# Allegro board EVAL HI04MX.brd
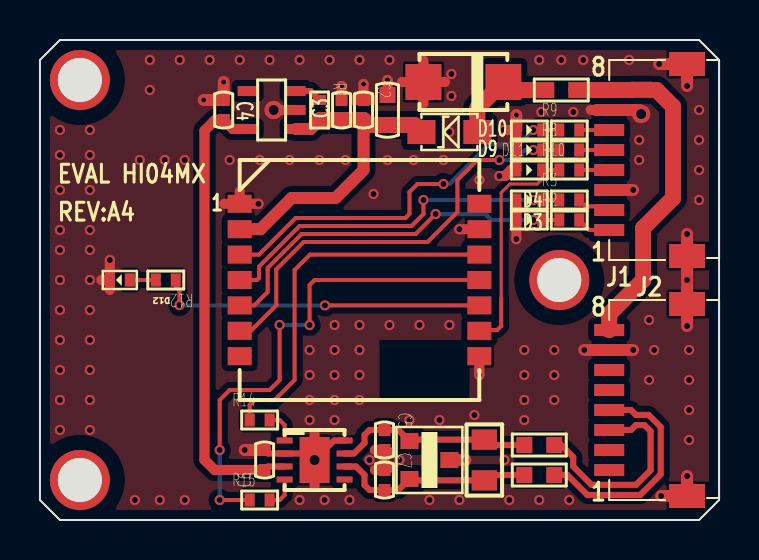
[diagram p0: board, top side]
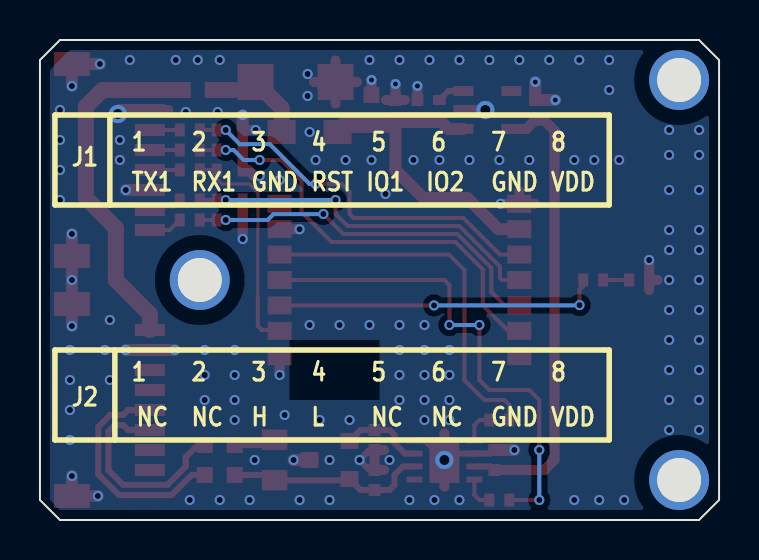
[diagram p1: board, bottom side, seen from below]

Outline 34 x 24 mm; copper layers: TOP, BOTTOM. Coordinates in mm from the lower left corner of the outline.
Outline path: 0,23 0,1 1,0 33,0 34,1 34,23 33,24 1,24 0,23

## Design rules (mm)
constraint set DEFAULT: min track width 0.152
net group CAN2: nets H L

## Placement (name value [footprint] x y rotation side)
C1  10uF  [C0603]  17.4 20.5 270 top
C2  0.1uF  [C0402]  16.2 20.5 270 top
C3  1uF  [C0402]  15.1 20.5 90 top
C4  1uF  [C0402]  9.2 20.5 270 top
C5  100pF  [C0402]  17.25 4 270 top
C6  0.1uF  [C0402]  11.25 3 90 top
C7  100pF  [C0402]  17.25 2 270 top
D1  RB160MM-60TR  [SOD123FL]  20.5 19.4 0 top
D2  SDD32A05L01  [DO-214AC]  21.2 21.9 180 top
D3  SBD52C05L01  [SOD-523]  24.5 15 0 top
D4  SBD52C05L01  [SOD-523]  24.5 16 0 top
D9  SBD52C05L01  [SOD-523]  24.5 18.5 0 top
D10  SBD52C05L01  [SOD-523]  24.5 19.5 0 top
D11  SBD52C05L01  [SOD-523]  24.5 17.5 0 top
D12  GREEN  [LED0402]  4 12 180 top
D13  SM24CANB-02HTG  [SOT23-3-0_95]  19.5 3 270 top
F1  100mA  [F0603]  25 3.75 180 top
F2  100mA  [F0603]  25 2.25 180 top
F3  300mA  [F0603]  26.1 21.5 180 top
H1  HOLE  [HOLE-2-MM]  2 22 0 top
H2  HOLE  [HOLE-2-MM]  2 2 0 top
H3  HOLE  [HOLE-2-MM]  26 12 0 top
J1  CON10  [5015680807_1]  28.5 18 270 top
J2  CON10  [5015680807_1]  28.5 6 270 top
R1  1K  [R0402]  14 20.5 270 top
R2  33R  [R0402]  26.5 15 0 top
R3  33R  [R0402]  26.5 16 0 top
R8  33R  [R0402]  26.5 18.5 0 top
R9  33R  [R0402]  26.5 19.5 0 top
R10  33R  [R0402]  26.5 17.5 0 top
R12  1K  [R0402]  6.3 12 180 top
R13  120R/DNP  [R0805]  22.25 3 90 top
R14  1K  [R0402]  11 5 0 top
R15  1K  [R0402]  11 1 0 top
U1  SPX3819M5-L-3-3/TR  [SOT23-5-0_95]  11.6 20.5 90 top
U2  HI04MX  [HI03_HI04MX]  16 12 0 top
U3  SIT3051TK  [HVSON8]  13.75 3 0 top

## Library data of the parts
C1-C7 = Capacity_Nonpolarity
D1 = diode
D2-D4 D9-D11 = DIODE BI-DIR TRIG
D12 = LED
D13 = BAT54A/SOT
F1-F3 = Fuse
H1-H3 = HOLE
J1 J2 = CON10
R1-R3 R8-R10 R12-R15 = Res
U1 = XC6210
U2 = HI04MX
U3 = SIT3051TK

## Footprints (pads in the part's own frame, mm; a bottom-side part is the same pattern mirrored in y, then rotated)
5015680807_1
  rect 0.6x1.5 smd: 1(3.5,0) 2(2.5,0) 3(1.5,0) 4(0.5,0) 5(-0.5,0) 6(-1.5,0) 7(-2.5,0) 8(-3.5,0)
  rect 1.2x1.8 smd: 9(4.8,3.9) 10(-4.8,3.9)
C0402
  rect 0.6x0.6 smd: 1(-0.5,0) 2(0.5,0)
C0603
  rect 0.8x0.8 smd: 1(-0.75,0) 2(0.75,0)
DO-214AC
  rect 1.8x1.8 smd: 1(2,0) 2(-2,0)
F0603
  rect 0.8x0.8 smd: 1(-0.75,0) 2(0.75,0)
HI03_HI04MX
  rect 1.2x0.9 smd: 1(-6,3.81) 2(-6,2.54) 3(-6,1.27) 4(-6,0) 5(-6,-1.27) 6(-6,-2.54) 7(-6,-3.81) 8(6,-3.81) 9(6,-2.54) 10(6,-1.27) 11(6,0) 12(6,1.27) 13(6,2.54) 14(6,3.81)
HOLE-2-MM
  round 3 hole 2.2: 1(0,0)
HVSON8
  rect 0.8x0.3 smd: 1(-1.5,0.975) 2(-1.5,0.325) 3(-1.5,-0.325) 4(-1.5,-0.975) 5(1.5,-0.975) 6(1.5,-0.325) 7(1.5,0.325) 8(1.5,0.975)
  rect 1.5x2.3 smd: 9(0,0)
LED0402
  rect 0.5x0.65 smd: 1(-0.5,0) 2(0.5,0)
R0402
  rect 0.5x0.65 smd: 1(-0.5,0) 2(0.5,0)
R0805
  rect 1.016x1.27 smd: 1(-1.016,0) 2(1.016,0)
SOD123FL
  rect 1.4x1.2 smd: 1(1.4,0) 2(-1.4,0)
SOD-523
  rect 0.5x0.65 smd: 1(-0.65,0) 2(0.65,0)
SOT23-3-0_95
  rect 0.8x0.9 smd: 1(-0.95,-1) 2(0.95,-1) 3(0,1)
SOT23-5-0_95
  rect 0.5x1 smd: 1(-0.95,-1.2) 2(0,-1.2) 3(0.95,-1.2) 4(0.95,1.2) 5(-0.95,1.2)

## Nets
GND: C1.1 C2.1 C3.2 C4.1 C5.2 C6.2 C7.1 D2.1 D3.1 D4.1 D9.1 D10.1 D11.1 D12.2(-) D13.3 J1.3 J1.7 J1.9 J1.10 J2.7 J2.9 J2.10 U1.2(VSS) U2.1 U2.8 U2.13 U3.2 U3.8 U3.9
VCC: F3.1 J1.8 J2.8
VDD: C1.2 C2.2 C3.1 D1.2 R1.2 U1.1 U2.2(VDD)
CAN_RX: R15.1 U2.11
CAN_TX: R14.1 U2.12
DP3V3: C4.2 C6.1 U1.5 U3.3(VCC)
H: F1.1 J2.3
IO1: D9.2 R8.1 U2.6
IO2: D10.2 R9.1 U2.3
IO5: R12.1 U2.10
IO_1: J1.5 R8.2
IO_2: J1.6 R9.2
L: F2.1 J2.4
NRST: J1.4 R10.2
RST: D11.2 R10.1 U2.9
RXD1: D4.2 R3.1 U2.4
TXD1: D3.2 R2.1 U2.5
USART1_RX: J1.2 R3.2
USART1_TX: J1.1 R2.2
N2198535: D12.1 R12.2
N2224750: R1.1 U1.3
N2242059: C5.1 D13.1 F1.2 R13.2 U3.7
N2242241: R14.2 U3.1
N2242331: C7.2 D13.2 F2.2 R13.1 U3.6
N2242381: R15.2 U3.4
N2269430: D1.1(P) D2.2 F3.2

Pads without a net: H1 1; H2 1; H3 1; J2 1 2 5 6; U1 4; U2 7 14; U3 5

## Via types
v1: diameter 0.508, hole 0.305, TOP to BOTTOM, 141 vias
v2: diameter 0.914, hole 0.508, TOP to BOTTOM, 3 vias
v3: diameter 0.508, hole 0.254, TOP to BOTTOM, 6 vias

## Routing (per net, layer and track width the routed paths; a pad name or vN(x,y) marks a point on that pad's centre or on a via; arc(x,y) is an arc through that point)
GND: length 52.6
  TOP w0.305: 12.25,3.33 U3.2 12.25,3.33 ; 12.25,3.33 13.42,3.33 v2(13.75,3) 14.72,3.97 U3.8 ; 12.25,3.33 11.42,3.33 C6.2 ; C7.1 17.5,2.5 v1(18,3) 17.5,3.5 C5.2
  TOP w0.5: 16.77,3.5 C5.2 17.25,3.02 ; 19.2,20.82 D2.1 ; D2.1 18.12,21.9 ; D2.1 19.2,22.98 ; D2.1 20.28,21.9 ; 10,16.44 U2.1 9.22,15.81 ; 29.43,20.5 J1.7 27.57,20.5 ; 3.5,11.5 D12.2 3.07,12 ; 13.75,4.33 v2(13.75,3) 13.75,1.67 ; 15.72,21 C2.1 16.68,21 ; 17.25,2.98 C7.1 16.77,2.5
  TOP w0.508: D12.2 v1(3.5,13) ; v1(23.85,14.05) D3.1 D4.1 ; U2.13 v1(21,14.54) ; U1.2 v2(11.7,20.5) ; C1.1 v3(17.4,22) ; U2.1 v1(10.94,15.81) ; C2.1 v3(16.2,21.8) ; C3.2 v3(15.1,21.7) ; v1(23.2,19.5) D10.1 D9.1 D11.1 23.58,17.5 23.28,17.2 v1(23,17.2) ; U2.8 v1(22,7.25)
  TOP w0.6: v1(31,22.8) J1.10 v1(32.4,21.7) ; v2(30.1,20.3) 30.1,20.4 30,20.5 J1.7 ; v3(9.2,21.9) C4.1 v3(8.2,21) ; v1(27.25,8.5) J2.7 v1(29.7,8.5) ; v1(32.4,2.2) J2.9 v1(31.1,1.2) ; J1.3 v1(29.7,16.5) ; D13.3 v1(21.3,3) ; C6.2 v1(10.25,3.5) ; D10.1 v3(23.85,20.25) ; v1(32.4,14.3) J1.9 v1(32.4,12) J2.10 v1(32.4,9.7)
  vias: v1(1,19.5) v1(1,18.25) v1(1,16.5) v1(1,14.5) v1(1,13.5) v1(1,12) v1(1,10.5) v1(1,9) v1(1,7.5) v1(1,6) v1(1,4.5) v1(2.5,19.5) v1(2.5,18.25) v1(2.5,16.5) v1(2.5,14.5) v1(2.5,13.5) v1(2.5,12) v1(2.5,10.5) v1(2.5,9) v1(2.5,7.5) v1(2.5,6) v1(2.5,4.5) v1(4.75,1) v1(5,18) v1(5.5,23) v1(5.5,21.5) v1(6,1) v1(6.25,18) v1(7,23) v1(7.25,18) v1(7.25,1) v1(8.5,23) v1(9.5,18) v1(10,23) v1(11,18) v1(11.5,23) v1(12.5,18) v1(13,23) v1(13,1) v1(13.5,8.5) v1(13.5,7.25) v1(13.5,6) v1(13.5,5) v1(14,18) v1(14.25,1) v1(14.5,23) v1(14.75,9.75) v1(14.75,8.5) v1(14.75,7.25) v1(14.75,6) v1(14.75,5) v1(15.3,18) v1(15.5,1) v1(16,23) v1(16,9.75) v1(16,8.5) v1(16,7.25) v1(16,6) v1(16.5,3) v1(16.7,16.3) v1(17.4,18) v1(17.5,23) v1(17.5,9.75) v1(18.5,5) v1(18.7,18) v1(19,9.75) v1(19.5,3) v1(19.5,1) v1(20,5) v1(20.2,18) v1(20.5,19.4) v1(20.5,9.75) v1(20.6,22.3) v1(20.6,21.2) v1(21,1) v1(21.75,5.25) v1(22,17) v1(23.25,3) v1(23.5,1) v1(24.25,8.5) v1(24.25,7.25) v1(24.25,6) v1(24.25,5) v1(25,23) v1(25,1) v1(25.1,20.4) v1(25.75,8.5) v1(25.75,7.25) v1(25.75,6) v1(26.1,23) v1(26.5,1) v1(26.7,20.4) v1(27.2,23) v1(29.5,23) v1(30,19) v1(30,18) v1(30.5,10) v1(30.5,7) v1(30.75,8.5) v1(32.5,8.5) v1(32.5,7) v1(32.5,5.5) v1(32.5,4) v1(33,20.5) v1(33,19) v1(33,17.5) v1(33,16)
VCC: length 17.7
  TOP w0.8: J2.8 28.5,10.3 30.2,12 30.2,14.6 31.7,16.1 31.7,20.67 30.87,21.5 30.57,21.5 30.56,21.51 29.64,21.51 29.63,21.5 J1.8 F3.1
VDD: length 16.7
  TOP w0.6: U1.1 13.55,19.55 R1.2 ; C2.2 16.2,17.5 14.8,16.1 12.6,16.1 11.04,14.54 U2.2
  TOP w0.8: D1.2 18.75,19.75 C1.2 16.45,19.75 C2.2 C3.1 R1.2
CAN_RX: length 24.8
  TOP w0.203: v1(9,3.5) 9,6 9.5,6.5 11.5,6.5 12,7 v1(12,9.75) ; v1(13.5,9.75) 13.5,11.75 13.75,12 U2.11 ; v1(9,1) R15.1
  BOTTOM w0.203: v1(9,3.5) v1(9,1) ; v1(13.5,9.75) v1(12,9.75)
CAN_TX: length 18.6
  TOP w0.203: U2.12 13.52,13.27 12.75,12.5 12.75,7 11.75,6 10.75,6 10.5,5.75 R14.1
DP3V3: length 23.3
  TOP w0.305: C6.1 11.42,2.68 U3.3
  TOP w0.508: C6.1 8.75,2.5 8.24,3.01 8.24,19.47 8.77,20 C4.2 9.65,19.55 U1.5
H: length 10.5
  TOP w0.305: F1.1 26.1,3.75 26.7,3.15 26.7,2.68 27.62,1.76 29.84,1.76 30.57,2.49 30.57,4.44 30.27,4.75 29.83,4.75 29.59,4.5 J2.3
IO1: length 21.7
  TOP w0.203: U2.6 10.56,9.46 11.83,10.73 11.83,12.53 13.2,13.9 19.4,13.9 20.9,15.4 20.9,17 21.9,18 v1(23,18) ; R8.1 D9.2 v1(24.7,18.5)
  BOTTOM w0.203: v1(24.7,18.5) 24.3,18.5 23.8,18 v1(23,18)
IO2: length 19.2
  TOP w0.203: U2.3 10.97,13.27 12.8,15.1 18.3,15.1 18.5,15.3 18.5,16.4 18.9,16.8 v1(20.2,16.8) ; v1(24.7,19.5) D10.2 R9.1
  BOTTOM w0.203: v1(20.2,16.8) 20.5,16.8 22.49,18.79 23.99,18.79 v1(24.7,19.5)
IO5: length 16.4
  TOP w0.203: v1(6.99,10.75) 6.99,11.51 6.8,11.7 R12.1 ; U2.10 v1(14.27,10.73)
  BOTTOM w0.203: v1(6.99,10.75) 7,10.73 v1(14.27,10.73)
IO_1: length 1.5
  TOP w0.203: J1.5 R8.2
IO_2: length 1.5
  TOP w0.203: J1.6 R9.2
L: length 11.5
  TOP w0.305: F2.1 26.41,2.25 27.41,1.25 30.05,1.25 31.08,2.28 31.08,4.65 30.48,5.25 29.83,5.25 29.59,5.5 J2.4
NRST: length 1.5
  TOP w0.203: R10.2 J1.4
RST: length 11.5
  TOP w0.152: 23.09,11.1 23.09,16.37 23.52,16.8 24.9,16.8 25.15,17.05 D11.2
  TOP w0.203: D11.2 R10.1 ; U2.9 22.04,9.5 22.89,9.5 23.09,9.7 23.09,11.1
RXD1: length 18.4
  TOP w0.203: v1(24.7,16) D4.2 R3.1 ; U2.4 10.87,12 10.97,12.1 10.97,12.67 13,14.7 18.6,14.7 19.2,15.3 v1(19.2,16)
  BOTTOM w0.203: v1(24.7,16) v1(19.2,16)
TXD1: length 18.7
  TOP w0.203: U2.5 10.73,10.73 11.4,11.4 11.4,12.6 13.1,14.3 18.81,14.3 v1(19.81,15.3) ; R2.1 D3.2 v1(24.7,15)
  BOTTOM w0.203: v1(19.81,15.3) 19.82,15.29 22.31,15.29 22.6,15 v1(24.7,15)
USART1_RX: length 1.7
  TOP w0.203: R3.2 27.32,15.68 28.32,15.68 J1.2
USART1_TX: length 1.7
  TOP w0.203: J1.1 27.5,14.5 R2.2
N2198535: length 1.3
  TOP w0.203: D12.1 R12.2
N2224750: length 1.4
  TOP w0.3: R1.1 13.55,21.45 U1.3
N2242059: length 10.1
  TOP w0.305: U3.7 15.25,3.33 15.72,3.33 16.25,3.85 16.25,4.25 16.5,4.5 C5.1 17.95,4.5 D13.1 18.57,4.02 R13.2 22.52,3.75 F1.2
N2242241: length 1.6
  TOP w0.203: R14.2 12,5 12.25,4.75 U3.1
N2242331: length 10.1
  TOP w0.305: F2.2 22.52,2.25 R13.1 18.57,1.98 D13.2 17.95,1.5 C7.2 16.5,1.5 16.25,1.75 16.25,2.25 15.82,2.68 U3.6
N2242381: length 1.6
  TOP w0.203: U3.4 12.25,1.25 12,1 R15.2
N2269430: length 5.4
  TOP w0.8: F3.2 23.6,21.5 D2.2 21.9,20.6 D1.1

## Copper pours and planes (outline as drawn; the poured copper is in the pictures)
GND on TOP: 1.5,23.5 32.5,23.5 33.5,22.5 33.5,1 33,0.5 1.5,0.5 0.5,1.5 0.5,22.5 ; 5 cut-outs
GND on BOTTOM: 1.5,23.5 32.5,23.5 33.5,22.5 33.5,1 33,0.5 1.5,0.5 0.5,1.5 0.5,22.5

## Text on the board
Ref Des/Silkscreen Bottom: 8 | VDD | 7 | GND | 6 | NC | IO2 | 5 | IO1 | 4 | RST | L | 3 | H | 2 | RX1 | 1 | TX1 | J1 | J2
Ref Des/Silkscreen Top: EVAL HI04MX | REV:A4 | 8 | 1 | J1 | J2
User.8: FIGURE | FINISHED_SIZE | 10.0 | 12.0 | 20.0 | 86.614 | DRILL CHART: TOP to BOTTOM | ALL UNITS ARE IN MILS | PLATED | QTY | 126 | 2 | 3
